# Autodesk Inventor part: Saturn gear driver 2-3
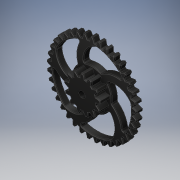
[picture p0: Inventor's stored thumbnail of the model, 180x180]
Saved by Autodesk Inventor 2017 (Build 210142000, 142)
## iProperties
Created: 2016-06
Part Number: Saturn gear driver 2-3
Material: Generic
Document SubType Name: Modeling
Designer: Stan
Density: 1 g/cm^3
Appearance: Glossy - Black
Author: Stan
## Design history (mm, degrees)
sketch "Sketch1" dims "d11" = 6.35
  geometry: A1 r 17.705 centre (23.133, -31.294) between (7.746, -40.053) and (10.358, -43.553); A2 r 17.705 centre (23.133, -31.294) between (7.746, -40.053) and (10.358, -43.553); A3 r 17.705 centre (-11.387, -37.213) between (4.743, -44.516) and (6.039, -40.346); A4 r 17.705 centre (-11.387, -37.213) between (4.743, -44.516) and (6.039, -40.346); A5 r 17.705 centre (28.089, -26.934) between (14.404, -38.168) and (17.57, -41.176); A6 r 17.705 centre (28.089, -26.934) between (14.404, -38.168) and (17.57, -41.176); A7 r 17.705 centre (-4.934, -38.602) between (12.198, -43.074) and (12.771, -38.745); A8 r 17.705 centre (-4.934, -38.602) between (12.198, -43.074) and (12.771, -38.745); A9 r 17.705 centre (32.237, -21.8) between (20.647, -35.184) and (24.276, -37.614); A10 r 17.705 centre (32.237, -21.8) between (20.647, -35.184) and (24.276, -37.614); A11 r 17.705 centre (1.661, -38.881) between (19.302, -40.393) and (19.135, -36.029); A12 r 17.705 centre (1.661, -38.881) between (19.302, -40.393) and (19.135, -36.029); A13 r 17.705 centre (35.458, -16.038) between (26.296, -31.189) and (30.284, -32.971); A14 r 17.705 centre (35.458, -16.038) between (26.296, -31.189) and (30.284, -32.971); A15 r 17.705 centre (8.208, -38.041) between (25.85, -36.55) and (24.949, -32.277); A16 r 17.705 centre (8.208, -38.041) between (25.85, -36.55) and (24.949, -32.277); A17 r 17.705 centre (37.658, -9.815) between (31.189, -26.296) and (35.42, -27.378); A18 r 17.705 centre (37.658, -9.815) between (31.189, -26.296) and (35.42, -27.378); A19 r 17.705 centre (14.519, -36.106) between (31.656, -31.656) and (30.045, -27.596); A20 r 17.705 centre (14.519, -36.106) between (31.656, -31.656) and (30.045, -27.596); A21 r 17.705 centre (38.775, -3.31) between (35.184, -20.647) and (39.537, -20.999); A22 r 17.705 centre (38.775, -3.31) between (35.184, -20.647) and (39.537, -20.999); A23 r 17.705 centre (20.412, -33.133) between (36.55, -25.85) and (34.276, -22.122); A24 r 17.705 centre (20.412, -33.133) between (36.55, -25.85) and (34.276, -22.122); A25 r 17.705 centre (38.777, 3.291) between (38.168, -14.404) and (42.518, -14.015); A26 r 17.705 centre (38.777, 3.291) between (38.168, -14.404) and (42.518, -14.015); A27 r 17.705 centre (25.718, -29.207) between (40.393, -19.302) and (37.522, -16.011); A28 r 17.705 centre (25.718, -29.207) between (40.393, -19.302) and (37.522, -16.011); A29 r 17.705 centre (37.663, 9.797) between (40.053, -7.746) and (44.274, -6.628); A30 r 17.705 centre (37.663, 9.797) between (40.053, -7.746) and (44.274, -6.628); A31 r 17.705 centre (30.284, -24.441) between (43.074, -12.198) and (39.688, -9.439); A32 r 17.705 centre (30.284, -24.441) between (43.074, -12.198) and (39.688, -9.439); A33 r 17.705 centre (35.465, 16.021) between (40.786, -0.866) and (44.758, 0.95); A34 r 17.705 centre (35.465, 16.021) between (40.786, -0.866) and (44.758, 0.95); A35 r 17.705 centre (33.979, -18.971) between (44.516, -4.743) and (40.713, -2.596); A36 r 17.705 centre (33.979, -18.971) between (44.516, -4.743) and (40.713, -2.596); A37 r 17.705 centre (32.248, 21.784) between (40.346, 6.039) and (43.953, 8.501); A38 r 17.705 centre (32.248, 21.784) between (40.346, 6.039) and (43.953, 8.501); A39 r 17.705 centre (36.696, -12.956) between (44.677, 2.849) and (40.566, 4.322); A40 r 17.705 centre (36.696, -12.956) between (44.677, 2.849) and (40.566, 4.322); A41 r 17.705 centre (28.102, 26.921) between (38.745, 12.771) and (41.884, 15.806); A42 r 17.705 centre (28.102, 26.921) between (38.745, 12.771) and (41.884, 15.806); A43 r 17.705 centre (38.358, -6.568) between (43.553, 10.358) and (39.252, 11.115); A44 r 17.705 centre (38.358, -6.568) between (43.553, 10.358) and (39.252, 11.115); A45 r 17.705 centre (23.148, 31.283) between (36.029, 19.135) and (38.611, 22.658); A46 r 17.705 centre (23.148, 31.283) between (36.029, 19.135) and (38.611, 22.658); A47 r 17.705 centre (38.916, 0.009) between (41.176, 17.57) and (36.809, 17.589); A48 r 17.705 centre (38.916, 0.009) between (41.176, 17.57) and (36.809, 17.589); A49 r 17.705 centre (17.529, 34.745) between (32.277, 24.949) and (34.226, 28.857); A50 r 17.705 centre (17.529, 34.745) between (32.277, 24.949) and (34.226, 28.857); A51 r 17.705 centre (38.355, 6.586) between (37.614, 24.276) and (33.307, 23.557); A52 r 17.705 centre (38.355, 6.586) between (37.614, 24.276) and (33.307, 23.557); A53 r 17.705 centre (11.404, 37.207) between (27.596, 30.045) and (28.857, 34.226); A54 r 17.705 centre (11.404, 37.207) between (27.596, 30.045) and (28.857, 34.226); A55 r 17.705 centre (36.69, 12.973) between (32.971, 30.284) and (28.847, 28.847); A56 r 17.705 centre (36.69, 12.973) between (32.971, 30.284) and (28.847, 28.847); A57 r 17.705 centre (4.952, 38.6) between (22.122, 34.276) and (22.658, 38.611); A58 r 17.705 centre (4.952, 38.6) between (22.122, 34.276) and (22.658, 38.611); A59 r 17.705 centre (33.97, 18.987) between (27.378, 35.42) and (23.557, 33.307); A60 r 17.705 centre (33.97, 18.987) between (27.378, 35.42) and (23.557, 33.307); A61 r 17.705 centre (-1.642, 38.881) between (16.011, 37.522) and (15.806, 41.884); A62 r 17.705 centre (-1.642, 38.881) between (16.011, 37.522) and (15.806, 41.884); A63 r 17.705 centre (30.272, 24.455) between (20.999, 39.537) and (17.589, 36.809); A64 r 17.705 centre (30.272, 24.455) between (20.999, 39.537) and (17.589, 36.809)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; 1 further point
  constraints: 652 point on circle, 326 centre point, 8 horizontal alignment, 910 other
extrude "Extrusion1" new body sketch "Sketch1" distance "d0" = 6.35; taper "d1" = 0 deg
sketch "Sketch2"
  geometry: A1 r 10.894 centre (-14.853, 0.29) between (-10.085, 10.085) and (-14.254, 11.167); A2 r 10.894 centre (-14.853, 0.29) between (-10.085, 10.085) and (-14.254, 11.167); A3 r 10.894 centre (1.502, 14.78) between (-9.368, 15.496) and (-8.796, 11.227); A4 r 10.894 centre (1.502, 14.78) between (-9.368, 15.496) and (-8.796, 11.227); A5 r 10.894 centre (-13.286, -6.646) between (-13.616, 4.243) and (-17.811, 3.264); A6 r 10.894 centre (-13.286, -6.646) between (-13.616, 4.243) and (-17.811, 3.264); A7 r 10.894 centre (-5.538, 13.785) between (-15.496, 9.368) and (-13.005, 5.853); A8 r 10.894 centre (-5.538, 13.785) between (-15.496, 9.368) and (-13.005, 5.853); A9 r 10.894 centre (-8.676, -12.059) between (-14.028, -2.571) and (-17.288, -5.387); A10 r 10.894 centre (-8.676, -12.059) between (-14.028, -2.571) and (-17.288, -5.387); A11 r 10.894 centre (-11.31, 9.632) between (-18.074, 1.093) and (-14.236, -0.861); A12 r 10.894 centre (-11.31, 9.632) between (-18.074, 1.093) and (-14.236, -0.861); A13 r 10.894 centre (-2.078, -14.71) between (-11.227, -8.796) and (-12.804, -12.804); A14 r 10.894 centre (-2.078, -14.71) between (-11.227, -8.796) and (-12.804, -12.804); A15 r 10.894 centre (-14.491, 3.273) between (-16.512, -7.432) and (-12.205, -7.378); A16 r 10.894 centre (-14.491, 3.273) between (-16.512, -7.432) and (-12.205, -7.378); A17 r 10.894 centre (4.996, -13.991) between (-5.853, -13.005) and (-5.387, -17.288); A18 r 10.894 centre (4.996, -13.991) between (-5.853, -13.005) and (-5.387, -17.288); A19 r 10.894 centre (-14.352, -3.836) between (-11.167, -14.254) and (-7.378, -12.205); A20 r 10.894 centre (-14.352, -3.836) between (-11.167, -14.254) and (-7.378, -12.205); A21 r 10.894 centre (10.925, -10.066) between (0.861, -14.236) and (3.264, -17.811); A22 r 10.894 centre (10.925, -10.066) between (0.861, -14.236) and (3.264, -17.811); A23 r 10.894 centre (-10.925, -10.066) between (-3.264, -17.811) and (-0.861, -14.236); A24 r 10.894 centre (-10.925, -10.066) between (-3.264, -17.811) and (-0.861, -14.236); A25 r 10.894 centre (14.352, -3.836) between (7.378, -12.205) and (11.167, -14.254); A26 r 10.894 centre (14.352, -3.836) between (7.378, -12.205) and (11.167, -14.254); A27 r 10.894 centre (-4.996, -13.991) between (5.387, -17.288) and (5.853, -13.005); A28 r 10.894 centre (-4.996, -13.991) between (5.387, -17.288) and (5.853, -13.005); A29 r 10.894 centre (14.491, 3.273) between (12.205, -7.378) and (16.512, -7.432); A30 r 10.894 centre (14.491, 3.273) between (12.205, -7.378) and (16.512, -7.432); A31 r 10.894 centre (2.078, -14.71) between (12.804, -12.804) and (11.227, -8.796); A32 r 10.894 centre (2.078, -14.71) between (12.804, -12.804) and (11.227, -8.796); A33 r 10.894 centre (11.31, 9.632) between (14.236, -0.861) and (18.074, 1.093); A34 r 10.894 centre (11.31, 9.632) between (14.236, -0.861) and (18.074, 1.093); A35 r 10.894 centre (8.676, -12.059) between (17.288, -5.387) and (14.028, -2.571); A36 r 10.894 centre (8.676, -12.059) between (17.288, -5.387) and (14.028, -2.571); A37 r 10.894 centre (5.538, 13.785) between (13.005, 5.853) and (15.496, 9.368); A38 r 10.894 centre (5.538, 13.785) between (13.005, 5.853) and (15.496, 9.368); A39 r 10.894 centre (13.286, -6.646) between (17.811, 3.264) and (13.616, 4.243); A40 r 10.894 centre (13.286, -6.646) between (17.811, 3.264) and (13.616, 4.243); A41 r 10.894 centre (-1.502, 14.78) between (8.796, 11.227) and (9.368, 15.496); A42 r 10.894 centre (-1.502, 14.78) between (8.796, 11.227) and (9.368, 15.496); A43 r 10.894 centre (14.853, 0.29) between (14.254, 11.167) and (10.085, 10.085); A44 r 10.894 centre (14.853, 0.29) between (14.254, 11.167) and (10.085, 10.085); A45 r 10.894 centre (-8.199, 12.389) between (2.571, 14.028) and (1.093, 18.074); A46 r 10.894 centre (-8.199, 12.389) between (2.571, 14.028) and (1.093, 18.074); A47 r 10.894 centre (13.017, 7.159) between (7.432, 16.512) and (4.243, 13.616); A48 r 10.894 centre (13.017, 7.159) between (7.432, 16.512) and (4.243, 13.616); A49 r 10.894 centre (1.502, 14.78) between (-9.368, 15.496) and (-8.796, 11.227); A50 r 10.894 centre (-14.853, 0.29) between (-10.085, 10.085) and (-14.254, 11.167); A51 r 10.894 centre (-5.538, 13.785) between (-15.496, 9.368) and (-13.005, 5.853); A52 r 10.894 centre (-13.286, -6.646) between (-13.616, 4.243) and (-17.811, 3.264); A53 r 10.894 centre (-11.31, 9.632) between (-18.074, 1.093) and (-14.236, -0.861); A54 r 10.894 centre (-8.676, -12.059) between (-14.028, -2.571) and (-17.288, -5.387); A55 r 10.894 centre (-14.491, 3.273) between (-16.512, -7.432) and (-12.205, -7.378); A56 r 10.894 centre (-2.078, -14.71) between (-11.227, -8.796) and (-12.804, -12.804); A57 r 10.894 centre (-14.352, -3.836) between (-11.167, -14.254) and (-7.378, -12.205); A58 r 10.894 centre (4.996, -13.991) between (-5.853, -13.005) and (-5.387, -17.288); A59 r 10.894 centre (-10.925, -10.066) between (-3.264, -17.811) and (-0.861, -14.236); A60 r 10.894 centre (10.925, -10.066) between (0.861, -14.236) and (3.264, -17.811); A61 r 10.894 centre (-4.996, -13.991) between (5.387, -17.288) and (5.853, -13.005); A62 r 10.894 centre (14.352, -3.836) between (7.378, -12.205) and (11.167, -14.254); A63 r 10.894 centre (2.078, -14.71) between (12.804, -12.804) and (11.227, -8.796); A64 r 10.894 centre (14.491, 3.273) between (12.205, -7.378) and (16.512, -7.432)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; 1 further point
  constraints: 208 point on circle, 104 centre point, 8 horizontal alignment, 304 other
extrude "Extrusion2" join sketch "Sketch2" distance "d2" = 9.525; taper "d3" = 0 deg
fillet "Fillet1" dims "d4" = 0.79375
fillet "Fillet2" dims "d5" = 0.79375
fillet "Fillet3" dims "d6" = 0.79375
fillet "Fillet4" dims "d7" = 0.79375
fillet "Fillet5" dims "d8" = 0.79375
fillet "Fillet6" dims "d9" = 0.79375
fillet "Fillet7" dims "d10" = 0.79375
body "Solid1"
